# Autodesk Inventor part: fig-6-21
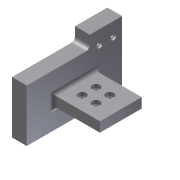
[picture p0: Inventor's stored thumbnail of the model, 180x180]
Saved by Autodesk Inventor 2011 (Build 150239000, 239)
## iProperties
Created: 2004-05
Part Number: fig-6-21
Document SubType Name: Modeling
Designer: CADCIM Technologies
Manufacturer: Standard
Standards Organization: Custom
Density: 1 g/cm^3
Author: CADCIM Technologies
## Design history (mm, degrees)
node "Sketch1"
sketch "Sketch2"
  geometry: L1 (0, 0)-(0, 26.557); L2 (0, 26.557)-(31.986, 26.557); L3 (31.986, 26.557)-(31.986, 32.916); L4 (31.986, 32.916)-(48.42, 32.916); L5 (48.42, 32.916)-(48.42, 0); L6 (48.42, 0)-(0, 0)
  constraints: 12 end point, 4 parallel, 1 perpendicular, 1 vertical
extrude "Extrusion1" new body sketch "Sketch2" distance "d0" = 7.5; taper "d1" = 0 deg
workplane "Work Plane1"
sketch "Sketch3"
  geometry: L1 (7.5, 35.088)-(30.78, 35.088); L2 (30.78, 35.088)-(30.78, 13.871); L3 (30.78, 13.871)-(7.5, 13.871); L4 (7.5, 31.986)-(7.5, 48.42) reference; L5 (7.5, 0)-(7.5, 31.986) reference
  constraints: 6 end point, 2 point on line, 1 horizontal, 1 parallel, 1 perpendicular
extrude "Extrusion2" join sketch "Sketch3" distance "d3" = 5; taper "d4" = 0 deg
fillet "Fillet2" dims "d7" = 2
fillet "Fillet3" dims "d8" = 2
hole "Hole1" diameter "d11" = 3; stored, may be unused: countersink angle "d15" = 90 deg, drill point angle "d17" = 118 deg; dims "d9" = 7, "d10" = 16, "d12" = 6, "d13" = 4, "d14" = 2, "d16" = 8
pattern_linear "Rectangular Pattern1" dims "d20" = 7, "d23" = 7
hole "Hole2" diameter "d26" = 2; stored, may be unused: countersink angle "d30" = 90 deg, drill point angle "d32" = 118 deg; dims "d24" = 5, "d25" = 7, "d27" = 6, "d28" = 3, "d29" = 1, "d31" = 8
pattern_linear "Rectangular Pattern2" dims "d35" = 7
body "Solid1"
other parameters: "d2" = -11
